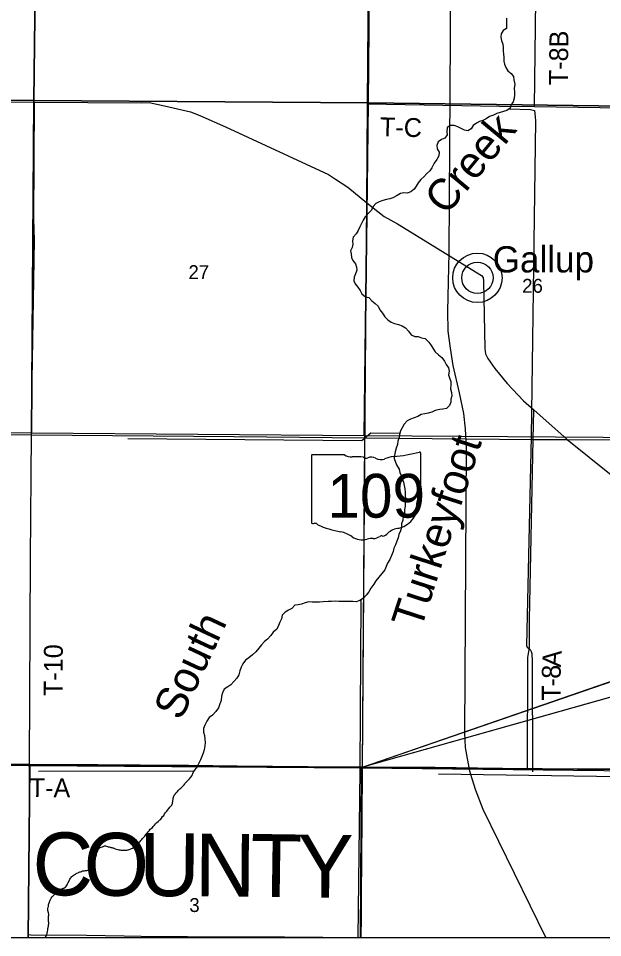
# Model space of a CAD drawing. Extents: x -6.2 to 37.4, y 0.2 to 22.2.
# Drawn here: x 5.67 to 6.55, y 14.307 to 15.692 of the extents above; entities that cross this region are included whole.
import ezdxf

# ---------------------------------------------------------------- set-up
doc = ezdxf.new("R2010")
doc.units = 0
for name, color, linetype in [('GM_X_County_Road', 7, 'Continuous'), ('GM_X_County_Text', 7, 'Continuous'), ('GM_X_Minor_River', 7, 'Continuous'), ('GM_X_Minor_River_Text', 7, 'Continuous'), ('GM_X_Rail_Line', 7, 'Continuous'), ('GM_X_Section', 7, 'Continuous'), ('GM_X_Section_Text', 7, 'Continuous'), ('GM_X_State_Location', 7, 'Continuous'), ('GM_X_State_Route', 7, 'Continuous'), ('GM_X_State_Shield', 7, 'Continuous'), ('GM_X_Township_Road', 7, 'Continuous'), ('GM_X_Township_Road_Text', 7, 'Continuous'), ('GM_X_Unincorporated', 7, 'Continuous'), ('GM_X_Unincorporated_Location', 7, 'Continuous'), ('GM_X_Unincorporated_Text', 7, 'Continuous'), ('GM_X_US_Shield', 7, 'Continuous'), ('SH_Border', 7, 'Continuous'), ('SH_Cut_Line', 7, 'Continuous'), ('SH_Data', 7, 'Continuous')]:
    doc.layers.add(name, color=color, linetype=linetype)

msp = doc.modelspace()

# ---------------------------------------------------------------- linework, layer by layer
at = {"layer": 'GM_X_County_Road'}
for points in [[(5.3585, 15.5042), (5.4617, 15.5613), (5.4694, 15.5646), (5.4865, 15.567), (5.5679, 15.5665), (5.6937, 15.5658), (5.8547, 15.5649), (5.8668, 15.5655), (5.8895, 15.5604), (5.9287, 15.5514), (5.9432, 15.5457), (5.9817, 15.5284), (6.1367, 15.4568), (6.1474, 15.4498), (6.1658, 15.4376), (6.1945, 15.414)], [(6.1945, 15.414), (6.2207, 15.3934), (6.2407, 15.3825), (6.3672, 15.3046), (6.3701, 15.3017), (6.3704, 15.296), (6.3726, 15.1947), (6.3732, 15.1867), (6.3767, 15.1796), (6.3873, 15.1646), (6.4059, 15.1418), (6.4305, 15.1161), (6.4462, 15.1023), (6.4966, 15.0575), (6.5957, 14.9778)], [(5.3613, 14.5708), (5.3746, 14.5707), (5.488, 14.5696), (5.5689, 14.569), (5.6863, 14.5681)]]:
    msp.add_lwpolyline(points, dxfattribs=at)
at = {"layer": 'GM_X_Minor_River'}
msp.add_line((6.184, 14.5597), (6.1809, 14.3074), dxfattribs=at)
for points in [[(6.405, 15.6923), (6.4049, 15.687), (6.4052, 15.6819), (6.4049, 15.6769), (6.3999, 15.6738), (6.3971, 15.6688), (6.3965, 15.6636), (6.3977, 15.6587), (6.3995, 15.6532), (6.4, 15.6484), (6.3998, 15.6431), (6.4007, 15.6381), (6.4008, 15.6334), (6.401, 15.6275), (6.4019, 15.6228), (6.4041, 15.618), (6.4072, 15.6132), (6.4121, 15.6091), (6.4154, 15.6043), (6.4162, 15.5993), (6.4174, 15.5929), (6.4167, 15.5864), (6.4172, 15.5815), (6.4173, 15.5765), (6.4166, 15.5716), (6.4152, 15.5663), (6.4115, 15.5615), (6.4104, 15.5566), (6.4054, 15.5534), (6.4004, 15.5515), (6.3953, 15.55), (6.3905, 15.5486), (6.3853, 15.5463), (6.3794, 15.5441), (6.3746, 15.5408), (6.3696, 15.5382), (6.3644, 15.5368), (6.3596, 15.5341), (6.3548, 15.5306), (6.352, 15.5255), (6.3466, 15.5224), (6.3417, 15.5234), (6.3368, 15.5262), (6.3316, 15.5284), (6.3261, 15.5304), (6.3208, 15.5305), (6.3156, 15.5275), (6.3151, 15.5213), (6.3155, 15.5165), (6.312, 15.5117), (6.307, 15.5095), (6.3022, 15.5058), (6.3, 15.5007), (6.3005, 15.4954), (6.3038, 15.4904), (6.3031, 15.4849), (6.3002, 15.4795), (6.296, 15.4739), (6.2925, 15.4671), (6.2897, 15.4622), (6.2849, 15.4582), (6.2806, 15.4533), (6.2758, 15.4492), (6.2721, 15.4444)], [(6.4087, 15.5555), (6.4412, 15.5548), (6.447, 15.5534), (6.4484, 15.5439), (6.4486, 15.5376), (6.4422, 15.0622), (6.4354, 14.7475), (6.4363, 14.745), (6.4406, 14.7415), (6.4421, 14.7386), (6.4431, 14.7354), (6.4434, 14.7316), (6.4439, 14.7272), (6.4444, 14.5569)], [(6.2721, 15.4444), (6.2691, 15.4395), (6.2658, 15.4346), (6.2608, 15.4306), (6.2554, 15.4286), (6.2503, 15.4293), (6.2453, 15.428), (6.2401, 15.4253), (6.234, 15.4216), (6.2292, 15.4204), (6.224, 15.419), (6.2189, 15.4177), (6.2131, 15.4158), (6.2082, 15.4132), (6.2039, 15.4084), (6.2015, 15.4029), (6.1964, 15.3981), (6.1922, 15.393), (6.1892, 15.3878), (6.1864, 15.3829), (6.1839, 15.378), (6.1813, 15.3726), (6.1787, 15.3677), (6.1742, 15.3625), (6.1728, 15.3568), (6.1735, 15.3519), (6.1724, 15.347), (6.1698, 15.3421), (6.1711, 15.3371), (6.1717, 15.332), (6.1735, 15.3272), (6.1774, 15.3224), (6.179, 15.3174), (6.1797, 15.3125), (6.1777, 15.3072), (6.1757, 15.3021), (6.1748, 15.2968), (6.1768, 15.2921), (6.181, 15.287), (6.1846, 15.282), (6.1873, 15.2772), (6.1927, 15.2726), (6.1976, 15.2715), (6.2021, 15.2667), (6.207, 15.2626), (6.2118, 15.2584), (6.2144, 15.253), (6.2184, 15.2482), (6.2217, 15.2426), (6.2262, 15.2378), (6.2313, 15.2345), (6.2365, 15.2323), (6.2422, 15.231), (6.2479, 15.229), (6.2529, 15.2259), (6.2572, 15.2207), (6.2613, 15.2155), (6.2667, 15.2129), (6.2719, 15.2126), (6.2768, 15.211), (6.2826, 15.2097), (6.288, 15.2043), (6.2917, 15.1995), (6.2976, 15.1899), (6.3026, 15.1851), (6.3075, 15.181), (6.3118, 15.1756), (6.3139, 15.1704), (6.3178, 15.1654), (6.3189, 15.1605), (6.3176, 15.1552), (6.319, 15.1504), (6.321, 15.1452), (6.3213, 15.1399), (6.3206, 15.1342), (6.3224, 15.1287), (6.3228, 15.1234), (6.3214, 15.1185), (6.3213, 15.1137), (6.3193, 15.1089), (6.3145, 15.1046), (6.3091, 15.1034), (6.3044, 15.1031), (6.2975, 15.1015), (6.2925, 15.0989), (6.2871, 15.0972), (6.2818, 15.0965), (6.2767, 15.0951), (6.2713, 15.0924), (6.2657, 15.0902), (6.2604, 15.0882), (6.2552, 15.0858), (6.2507, 15.0806), (6.2452, 15.0705), (6.2439, 15.0654), (6.2435, 15.0605), (6.2414, 15.0552), (6.241, 15.0501), (6.2386, 15.0444), (6.2375, 15.039), (6.2361, 15.0337)], [(6.2442, 15.0665), (6.2007, 15.0672), (6.1873, 15.0557), (5.8344, 15.0589)], [(6.2361, 15.0337), (6.236, 15.0289), (6.2392, 15.0194), (6.2432, 15.013), (6.2443, 15.0081), (6.2461, 15.0033), (6.2479, 14.9984), (6.2497, 14.9936), (6.2509, 14.9886), (6.2516, 14.9835), (6.2522, 14.9785), (6.2525, 14.9738), (6.2528, 14.9681), (6.2526, 14.9624), (6.2522, 14.9575), (6.2513, 14.9524), (6.2514, 14.9471), (6.2494, 14.942), (6.2487, 14.9363), (6.2469, 14.9305), (6.2469, 14.9253), (6.2451, 14.9199), (6.2429, 14.9148), (6.2417, 14.9097), (6.2397, 14.9044), (6.2377, 14.8992), (6.2351, 14.8939), (6.2342, 14.889), (6.2316, 14.8832), (6.2292, 14.8769), (6.2259, 14.8713), (6.2237, 14.8664), (6.2215, 14.8612), (6.2174, 14.8559), (6.2129, 14.8503), (6.2082, 14.8447), (6.2049, 14.8397), (6.2006, 14.8339), (6.1977, 14.8282), (6.1936, 14.8234), (6.1895, 14.8185), (6.1839, 14.8154), (6.1785, 14.8131), (6.1734, 14.8137), (6.1683, 14.8137), (6.1624, 14.8136), (6.1576, 14.8135), (6.1523, 14.8136), (6.147, 14.8141), (6.1415, 14.8138), (6.1364, 14.8137), (6.1288, 14.8131), (6.1234, 14.8125), (6.1185, 14.8126), (6.1124, 14.8127), (6.1071, 14.813), (6.1017, 14.8116), (6.0964, 14.8096), (6.0909, 14.8089), (6.0859, 14.8081), (6.0814, 14.8032), (6.0766, 14.8007), (6.0714, 14.7977), (6.067, 14.7929), (6.0661, 14.7876), (6.0635, 14.7825), (6.0615, 14.7773), (6.0591, 14.7722), (6.0537, 14.7675), (6.0498, 14.7623), (6.0451, 14.7569), (6.0403, 14.7532), (6.0357, 14.7484), (6.0318, 14.7433), (6.0271, 14.7381), (6.0222, 14.7331), (6.0166, 14.7286), (6.0118, 14.7253), (6.0077, 14.7199), (6.005, 14.7146), (6.0031, 14.7092), (6.0015, 14.7031), (5.9985, 14.6981), (5.9944, 14.6932), (5.9898, 14.6882), (5.985, 14.6853), (5.9798, 14.6814), (5.9772, 14.6761), (5.9756, 14.671), (5.9749, 14.6648), (5.9731, 14.6595), (5.971, 14.6537), (5.9671, 14.6479), (5.9621, 14.6426), (5.9572, 14.6391), (5.9533, 14.6335), (5.9504, 14.6275), (5.9485, 14.6222), (5.9486, 14.6171), (5.9499, 14.612), (5.9507, 14.6063)], [(6.1854, 14.8163), (6.184, 14.5597)], [(5.9507, 14.6063), (5.951, 14.6015), (5.9503, 14.5962), (5.9494, 14.5905), (5.9482, 14.5852), (5.9462, 14.5804), (5.9438, 14.5753), (5.9416, 14.57), (5.9388, 14.5651), (5.9375, 14.5624)], [(5.6997, 14.5581), (5.6999, 14.5583), (5.9347, 14.5585)], [(5.8207, 14.4396), (5.8224, 14.4395), (5.8241, 14.4393), (5.8262, 14.4391), (5.8279, 14.4389), (5.8295, 14.439), (5.8308, 14.439), (5.8321, 14.439), (5.8331, 14.439), (5.8344, 14.4395), (5.8356, 14.4395), (5.8367, 14.44), (5.8382, 14.4408), (5.8402, 14.4415), (5.8415, 14.442), (5.8438, 14.4439), (5.8455, 14.4448), (5.8471, 14.4461), (5.8481, 14.447), (5.849, 14.4481), (5.85, 14.4491), (5.8512, 14.4504), (5.8529, 14.4522), (5.8543, 14.4537), (5.8556, 14.4552), (5.8568, 14.4565), (5.8582, 14.4584), (5.8599, 14.4601), (5.8613, 14.4618), (5.8622, 14.4631), (5.8638, 14.4648), (5.8652, 14.4666), (5.8665, 14.4683), (5.8679, 14.4706), (5.8698, 14.4719), (5.8714, 14.4733), (5.8727, 14.475), (5.8745, 14.4769), (5.8762, 14.4788), (5.8784, 14.4806), (5.8803, 14.4823), (5.8818, 14.4836), (5.8828, 14.4847), (5.884, 14.4858), (5.8852, 14.4873), (5.8869, 14.4896), (5.8885, 14.4916), (5.8896, 14.4937), (5.8914, 14.4959), (5.893, 14.498), (5.8943, 14.4993), (5.8968, 14.5023), (5.8978, 14.5038), (5.8994, 14.5053), (5.9007, 14.507), (5.9015, 14.5085), (5.9017, 14.5094), (5.902, 14.5107), (5.9022, 14.5124), (5.9024, 14.5136), (5.9026, 14.5162), (5.9028, 14.5177), (5.9031, 14.5191), (5.9037, 14.5206), (5.9043, 14.5219), (5.9052, 14.5232), (5.9062, 14.5241), (5.907, 14.5253), (5.9081, 14.5264), (5.9093, 14.5275), (5.9105, 14.529), (5.912, 14.5303), (5.913, 14.5314), (5.9145, 14.5327), (5.9159, 14.534), (5.9175, 14.5357), (5.9184, 14.5366), (5.9194, 14.5377), (5.9204, 14.5389), (5.921, 14.54), (5.9227, 14.542), (5.9239, 14.5432), (5.9254, 14.5446), (5.9264, 14.5458), (5.9272, 14.5467), (5.9287, 14.5484), (5.9295, 14.5493), (5.9313, 14.5518), (5.9319, 14.5534), (5.9323, 14.5546), (5.9329, 14.5559), (5.9375, 14.5624)], [(6.3025, 14.5539), (7.0849, 14.5425), (7.1095, 14.5424)], [(5.7151, 14.3573), (5.7155, 14.3584), (5.7161, 14.3599), (5.7165, 14.3611), (5.7169, 14.3624), (5.7175, 14.3637), (5.7181, 14.3648), (5.7191, 14.3667), (5.7205, 14.369), (5.7214, 14.3701), (5.7224, 14.371), (5.7238, 14.3725), (5.7247, 14.3734), (5.7259, 14.3746), (5.7269, 14.3753), (5.7284, 14.3766), (5.7301, 14.3779), (5.7313, 14.3786), (5.7328, 14.3796), (5.7338, 14.3803), (5.735, 14.3808), (5.7359, 14.3812), (5.7371, 14.3818), (5.7382, 14.3821), (5.7396, 14.3827), (5.7405, 14.3832), (5.7413, 14.3841), (5.7423, 14.3856), (5.7431, 14.3868), (5.7437, 14.3885), (5.7446, 14.3905), (5.7464, 14.3941), (5.747, 14.3954), (5.7482, 14.3969), (5.749, 14.3979), (5.7498, 14.3995), (5.7511, 14.3999), (5.7519, 14.4008), (5.7534, 14.4019), (5.7544, 14.4027), (5.7555, 14.4032), (5.7567, 14.404), (5.7577, 14.4043), (5.7594, 14.4052), (5.7603, 14.4056), (5.7621, 14.4063), (5.7632, 14.4067), (5.7646, 14.4072), (5.7661, 14.4078), (5.7672, 14.4079), (5.7691, 14.4081), (5.7707, 14.4084), (5.7716, 14.4086), (5.7728, 14.4086), (5.7739, 14.409), (5.7756, 14.4091), (5.777, 14.4095), (5.7781, 14.4096), (5.7793, 14.4098), (5.7804, 14.4105), (5.7819, 14.4109), (5.7821, 14.4118), (5.7827, 14.4137), (5.7835, 14.4152), (5.7838, 14.4165), (5.7842, 14.4175), (5.7846, 14.4192), (5.7846, 14.4203), (5.785, 14.4218), (5.785, 14.423), (5.7852, 14.4245), (5.7859, 14.427), (5.7863, 14.4292), (5.7871, 14.4319), (5.7871, 14.4328), (5.7875, 14.4339), (5.7879, 14.4358), (5.7887, 14.4373), (5.7891, 14.4385), (5.7903, 14.4405), (5.7913, 14.4415), (5.792, 14.4424), (5.793, 14.443), (5.7965, 14.4444), (5.7984, 14.4453), (5.7995, 14.4455), (5.801, 14.4455), (5.8022, 14.4454), (5.8037, 14.4448), (5.805, 14.4444), (5.8065, 14.4444), (5.8077, 14.4436), (5.809, 14.4434), (5.8103, 14.4432), (5.8116, 14.4428), (5.8126, 14.4424), (5.8143, 14.4418), (5.8156, 14.4412), (5.8173, 14.4408), (5.8192, 14.4402), (5.8207, 14.4396)], [(5.7102, 14.3074), (5.7106, 14.308), (5.7114, 14.3095), (5.7118, 14.3107), (5.7122, 14.3118), (5.713, 14.314), (5.7134, 14.3165), (5.7138, 14.3186), (5.714, 14.3209), (5.7147, 14.3248), (5.7149, 14.3267), (5.7153, 14.3284), (5.7154, 14.33), (5.715, 14.3317), (5.7151, 14.3341), (5.7151, 14.3364), (5.7151, 14.3381), (5.715, 14.3396), (5.7152, 14.3413), (5.7152, 14.3427), (5.7151, 14.3448), (5.714, 14.3482), (5.7138, 14.3501), (5.714, 14.3514), (5.7145, 14.3533), (5.7147, 14.3543), (5.7147, 14.3556), (5.7151, 14.3573)]]:
    msp.add_lwpolyline(points, dxfattribs=at)
at = {"layer": 'GM_X_Rail_Line'}
for points in [[(6.3497, 14.5582), (6.3432, 14.5938), (6.3423, 14.6161), (6.345, 15.0461), (6.3432, 15.0739), (6.3409, 15.0967), (6.3343, 15.1278), (6.3245, 15.1689), (6.3205, 15.1954), (6.3173, 15.2211), (6.3168, 15.251), (6.3186, 15.3389), (6.3232, 16.0678)], [(7.1861, 14.554), (7.1627, 14.5545), (7.0271, 14.5564), (7.0244, 14.5567), (7.0166, 14.557), (6.9389, 14.5582), (6.7664, 14.5594), (6.6888, 14.5602), (6.5644, 14.561), (6.4587, 14.5616), (6.4366, 14.5618), (6.3613, 14.5626), (6.2975, 14.5634), (6.1887, 14.5642), (6.188, 14.5642), (6.1064, 14.5648), (5.9991, 14.5656), (5.9261, 14.5666), (5.853, 14.567), (5.7893, 14.5675), (5.6862, 14.5684), (5.5688, 14.5693)], [(5.5688, 14.5693), (5.6862, 14.5684), (5.7893, 14.5675), (5.853, 14.567), (5.9261, 14.5666), (5.9991, 14.5656), (6.1064, 14.5648), (6.188, 14.5642), (6.1887, 14.5642), (6.2975, 14.5634), (6.3613, 14.5626), (6.4366, 14.5618), (6.4587, 14.5616), (6.5644, 14.561), (6.6888, 14.5602), (6.7664, 14.5594), (6.9389, 14.5582), (7.0166, 14.557), (7.0244, 14.5567), (7.0271, 14.5564), (7.1627, 14.5545), (7.1861, 14.554)], [(6.4645, 14.3074), (6.3701, 14.5003), (6.3581, 14.5306), (6.3511, 14.5529), (6.3497, 14.5582)], [(5.0809, 14.3074), (7.1878, 14.3074)]]:
    msp.add_lwpolyline(points, dxfattribs=at)
at = {"layer": 'GM_X_Section'}
for points in [[(5.6991, 16.0714), (5.6928, 15.5685), (5.1903, 15.5715), (5.1946, 16.0748)], [(6.201, 16.0668), (6.1968, 15.5647), (5.6928, 15.5685), (5.6991, 16.0714)], [(6.7037, 16.063), (6.6989, 15.5603), (6.6989, 15.5584), (6.1968, 15.5647), (6.201, 16.0668)], [(5.1903, 15.5715), (5.6928, 15.5685), (5.6894, 15.0671), (5.1846, 15.0717)], [(5.6928, 15.5685), (6.1968, 15.5647), (6.1906, 15.0632), (5.6894, 15.0671)], [(6.1968, 15.5647), (6.6989, 15.5584), (6.6946, 15.0595), (6.1906, 15.0632)]]:
    msp.add_lwpolyline(points, close=True, dxfattribs=at)
at = {"layer": 'GM_X_State_Route'}
for points in [[(6.1881, 14.564), (6.1917, 15.0602), (6.1945, 15.414), (6.1957, 15.5633), (6.1996, 16.064), (6.2033, 16.5415), (6.2023, 16.5714)], [(6.1863, 14.3074), (6.1863, 14.3076), (6.1865, 14.3387), (6.1868, 14.3744), (6.1872, 14.4226), (6.1877, 14.4925), (6.188, 14.5547), (6.1881, 14.5623), (6.1881, 14.564)]]:
    msp.add_lwpolyline(points, dxfattribs=at)
at = {"layer": 'GM_X_State_Shield'}
for p, q in [((6.2758, 14.9849), (6.2758, 15.0372)), ((6.111, 15.033), (6.111, 14.9329)), ((6.1609, 15.0347), (6.1126, 15.0347)), ((6.2757, 14.9849), (6.2758, 14.9849))]:
    msp.add_line(p, q, dxfattribs=at)
for centre, major_axis, start_param, end_param in [((6.2171, 15.1711), (0.1748, 0), 4.814394, 5.042369), ((6.2739, 15.0374), (0.00183, 0), 6.141152, 7.989035), ((6.1129, 15.0332), (0.00191, 0), 1.712693, 3.28349), ((6.1723, 15.0463), (0.0185, 0), 4.042523, 4.731795), ((6.1785, 14.9785), (0.0665, 0), 1.404758, 1.657858), ((6.1936, 15.0337), (0.00534, 0), 3.836095, 5.185415), ((6.2014, 15.0222), (0.0111, 0), 0.950623, 2.079405), ((6.2158, 15.038), (0.0134, 0), 4.081561, 5.145723), ((6.2394, 15.0042), (0.0352, 0), 1.699011, 2.107814), ((6.2753, 14.981), (0.00284, 0), 1.883978, 3.671073), ((6.2738, 14.9846), (0.00196, 0), 5.05454, 6.418171), ((6.2823, 14.9629), (0.0124, 0), 2.387724, 3.262537), ((6.2573, 14.9744), (0.017, 0), 5.934695, 6.695948), ((6.2269, 14.9563), (0.0437, 0), 5.101752, 6.440018), ((6.1129, 14.9327), (0.00193, 0), 3.00124, 4.508301), ((6.1132, 14.943), (0.0147, 0), 4.665946, 4.897461), ((6.1162, 14.9272), (0.0053, 0), 0.519207, 1.627899), ((6.1831, 15.0171), (0.1262, 0), 4.195997, 4.488961), ((6.1455, 14.888), (0.0395, 0), 0.823519, 1.323587), ((6.2045, 14.9192), (0.0133, 0), 4.691044, 5.507374), ((6.2166, 14.9095), (0.00376, 0), 1.147584, 2.315152), ((6.215, 14.9232), (0.0141, 0), 4.937069, 5.64225), ((6.2453, 14.9048), (0.0239, 0), 1.647645, 2.488434), ((6.1882, 14.9267), (0.0251, 0), 4.026481, 4.996735), ((6.2026, 14.8921), (0.0206, 0), 1.495662, 1.94098)]:
    msp.add_ellipse(centre, major_axis=major_axis, ratio=0.8, start_param=start_param, end_param=end_param, dxfattribs=at)
at = {"layer": 'GM_X_Township_Road'}
msp.add_line((6.1863, 14.3076), (6.1938, 14.3074), dxfattribs=at)
for points in [[(6.4474, 15.559), (6.4513, 15.8799), (6.4516, 15.9282)], [(5.6894, 15.0647), (5.6902, 15.1476), (5.6936, 15.3578), (5.6926, 15.3899), (5.6937, 15.5658)], [(6.1957, 15.5633), (6.3943, 15.5597), (6.4474, 15.559), (6.6121, 15.5566), (6.6987, 15.5585)], [(6.4397, 14.7708), (6.4398, 14.7864), (6.4453, 15.0577), (6.4462, 15.1023)], [(5.3607, 15.0673), (5.6894, 15.0647), (5.9948, 15.062), (6.1917, 15.0602)], [(5.6863, 14.5681), (5.6878, 14.879), (5.6894, 15.0647)], [(6.1917, 15.0602), (6.4453, 15.0577), (6.4966, 15.0575), (6.6951, 15.0571)], [(6.4367, 14.5616), (6.4372, 14.7291), (6.4395, 14.7445), (6.4397, 14.7659), (6.4397, 14.7708)], [(5.3613, 14.5708), (5.3746, 14.5707), (5.488, 14.5696), (5.5689, 14.569), (5.6863, 14.5681)], [(5.6849, 14.3119), (5.685, 14.3295), (5.6852, 14.3683), (5.6855, 14.4072), (5.6856, 14.4305), (5.6858, 14.4554), (5.686, 14.4756), (5.6861, 14.4958), (5.6863, 14.5114), (5.6862, 14.5253), (5.6863, 14.5681)], [(5.6863, 14.5681), (5.7894, 14.5673), (5.8531, 14.5668), (5.9262, 14.5664), (5.9992, 14.5653), (6.1065, 14.5645), (6.1881, 14.564)], [(6.1881, 14.564), (6.1889, 14.564), (6.2977, 14.5631), (6.3554, 14.5624)], [(6.3554, 14.5624), (6.3614, 14.5623), (6.4367, 14.5616)], [(6.4367, 14.5616), (6.4588, 14.5614), (6.5645, 14.5607), (6.6889, 14.56)], [(5.6848, 14.3074), (5.6848, 14.3077), (5.6849, 14.3119)], [(5.6849, 14.3119), (5.6883, 14.3118), (5.7722, 14.3109), (5.8289, 14.3101)], [(5.8289, 14.3101), (5.8545, 14.3098), (5.9244, 14.3092), (6.0006, 14.3085), (6.035, 14.3084)], [(6.035, 14.3084), (6.0704, 14.3084), (6.1863, 14.3076)]]:
    msp.add_lwpolyline(points, dxfattribs=at)
at = {"layer": 'GM_X_Unincorporated'}
for radius in [0.0372, 0.0236]:
    msp.add_circle((6.3612, 15.3012), radius, dxfattribs=at)
at = {"layer": 'GM_X_Unincorporated_Location'}
msp.add_line((6.3612, 15.3012), (6.3612, 15.3012), dxfattribs=at)
at = {"layer": 'GM_X_US_Shield'}
for points in [[(5.1745, 14.3074), (5.6844, 14.3074), (5.6866, 14.5661), (5.6845, 14.5662), (5.1769, 14.57)], [(5.6844, 14.3074), (6.185, 14.3074), (6.1868, 14.5627), (5.6866, 14.5661)], [(6.185, 14.3074), (6.6867, 14.3074), (6.6887, 14.557), (6.1868, 14.5627)]]:
    msp.add_lwpolyline(points, close=True, dxfattribs=at)
at = {"layer": 'SH_Border'}
for p, q in [((6.1881, 14.564), (8.9944, 15.5335)), ((8.9944, 15.3553), (6.1881, 14.564))]:
    msp.add_line(p, q, dxfattribs=at)
at = {"layer": 'SH_Cut_Line'}
for points in [[(7.1861, 14.554), (7.1627, 14.5545), (7.0271, 14.5564), (7.0244, 14.5567), (7.0166, 14.557), (6.9389, 14.5582), (6.7664, 14.5594), (6.6888, 14.5602), (6.5644, 14.561), (6.4587, 14.5616), (6.4366, 14.5618), (6.3613, 14.5626), (6.2975, 14.5634), (6.1887, 14.5642), (6.188, 14.5642), (6.1064, 14.5648), (5.9991, 14.5656), (5.9261, 14.5666), (5.853, 14.567), (5.7893, 14.5675), (5.6862, 14.5684), (5.5688, 14.5693)], [(5.5688, 14.5693), (5.6862, 14.5684), (5.7893, 14.5675), (5.853, 14.567), (5.9261, 14.5666), (5.9991, 14.5656), (6.1064, 14.5648), (6.188, 14.5642), (6.1887, 14.5642), (6.2975, 14.5634), (6.3613, 14.5626), (6.4366, 14.5618), (6.4587, 14.5616), (6.5644, 14.561), (6.6888, 14.5602), (6.7664, 14.5594), (6.9389, 14.5582), (7.0166, 14.557), (7.0244, 14.5567), (7.0271, 14.5564), (7.1627, 14.5545), (7.1861, 14.554)], [(5.0809, 14.3074), (8.4809, 14.3074)]]:
    msp.add_lwpolyline(points, dxfattribs=at)
at = {"layer": 'SH_Data'}
msp.add_line((1.6809, 14.3074), (8.4809, 14.3074), dxfattribs=at)
msp.add_lwpolyline([(6.1881, 14.564), (6.1925, 15.1616), (6.1954, 15.5245), (6.2021, 16.3804), (6.2023, 16.5714)], dxfattribs=at)
msp.add_lwpolyline([(8.9944, 15.3553), (6.1881, 14.564), (8.9944, 15.5335)], close=True, dxfattribs=at)

# ---------------------------------------------------------------- texts
at = {"layer": 'GM_X_County_Text'}
for s, rotation, p in [('C', 359.5889, (5.6905, 14.3714)), ('O', 359.5998, (5.7676, 14.3708)), ('U', 359.5955, (5.8514, 14.3702)), ('N', 359.5346, (5.9351, 14.3696)), ('T', 359.1771, (6.0187, 14.369)), ('Y', 359.6042, (6.0897, 14.3679))]:
    msp.add_text(s, height=0.0947, rotation=rotation, dxfattribs=at).set_placement(p)
at = {"layer": 'GM_X_Minor_River_Text'}
for s, rotation, p in [('Creek', 50.3392, (6.3142, 15.3937)), ('Turkeyfoot', 72.0329, (6.2759, 14.7697)), ('South', 64.9198, (5.9144, 14.6327))]:
    msp.add_text(s, height=0.04737, rotation=rotation, dxfattribs=at).set_placement(p)
at = {"layer": 'GM_X_Section_Text'}
for s, height, p in [('27', 0.02093, (5.9258, 15.2993)), ('26', 0.02093, (6.4287, 15.2787)), ('3', 0.0209, (5.9272, 14.346))]:
    msp.add_text(s, height=height, rotation=0, dxfattribs=at).set_placement(p)
at = {"layer": 'GM_X_State_Location'}
msp.add_text('109', height=0.0000947, rotation=0, dxfattribs=at).set_placement((6.1581, 14.9694))
for s in ['s', 'r']:
    msp.add_text(s, height=0.0000947, dxfattribs=at).set_placement((6.1915, 14.9763))
at = {"layer": 'GM_X_State_Shield'}
msp.add_text('109', height=0.06592, dxfattribs=at).set_placement((6.1352, 14.94))
at = {"layer": 'GM_X_Township_Road_Text'}
for s, height, rotation, p in [('T-8B', 0.02841, 89.3481, (6.4974, 15.5912)), ('T-C', 0.02841, 358.7165, (6.2141, 15.5145)), ('T-10', 0.02841, 89.6452, (5.7361, 14.6711)), ('A', 0.0284, 86.3073, (6.4868, 14.7142)), ('8', 0.0284, 89.3131, (6.4866, 14.6971)), ('-', 0.0284, 89.8595, (6.4866, 14.6855)), ('T', 0.0284, 89.9828, (6.4866, 14.6643)), ('T-A', 0.02841, 359.588, (5.6865, 14.5191))]:
    msp.add_text(s, height=height, rotation=rotation, dxfattribs=at).set_placement(p)
at = {"layer": 'GM_X_Unincorporated_Text'}
msp.add_text('Gallup', height=0.03949, rotation=0, dxfattribs=at).set_placement((6.3843, 15.3093))

doc.saveas('drawing.dxf')
